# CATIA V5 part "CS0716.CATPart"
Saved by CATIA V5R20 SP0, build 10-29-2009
Part number: CS0716
Revision: 3
Definition: design
Nomenclature: CS0716
Source: made
Description: NOT SPECIFIED
Bounding box of the stored display mesh (mm): x -15 to 15, y -15 to 15, z -28 to 7.5
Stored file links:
  C:\Users\Raffaele\Desktop\3D X SITO CF\BOLEX\20-TILTED COLUMN SUPPORT\CS0716.CATPart
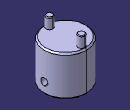
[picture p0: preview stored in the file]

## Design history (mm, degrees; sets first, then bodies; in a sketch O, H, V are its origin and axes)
Body1 "MANIFOLD_SOLID_BREP #691" (main body)
  Solid1: solid without history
